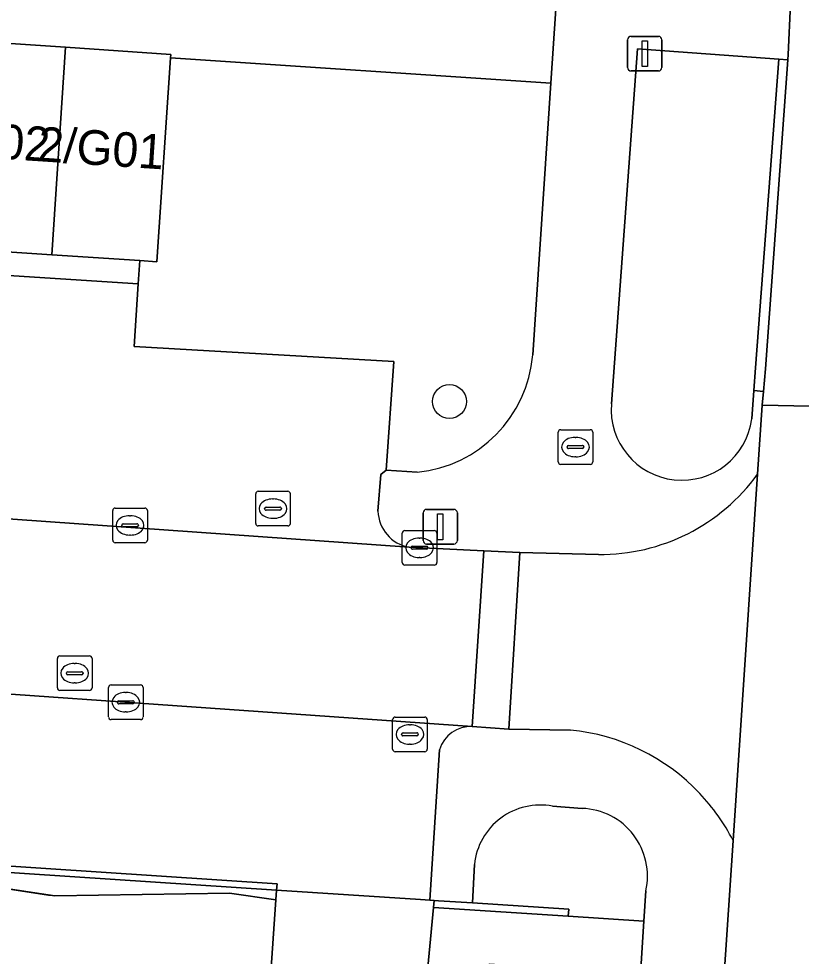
# Model space of a CAD drawing. Extents: x 161848 to 162726, y 385382 to 386521.
# Drawn here: x 162009.72 to 162032.32, y 385995.3 to 386022.36 of the extents above; entities that cross this region are included whole.
import ezdxf

# ---------------------------------------------------------------- set-up
doc = ezdxf.new("R2010")
doc.units = 0
for name, color, linetype in [('IMGEO_Boom', 7, 'Continuous'), ('IMGEO_Brandkraan', 7, 'Continuous'), ('IMGEO_Erf', 7, 'Continuous'), ('IMGEO_Fietspad_gesloten', 7, 'Continuous'), ('IMGEO_Groenvoorziening', 7, 'Continuous'), ('IMGEO_Kolk', 7, 'Continuous'), ('IMGEO_Lichtmast', 7, 'Continuous'), ('IMGEO_Muur', 7, 'Continuous'), ('IMGEO_Pand', 7, 'Continuous'), ('IMGEO_Pand_nummerreeks', 7, 'Continuous'), ('IMGEO_Pand_overbouw', 7, 'Continuous'), ('IMGEO_Parkeervlak_open', 7, 'Continuous'), ('IMGEO_Rijbaan_lokaal_open', 7, 'Continuous'), ('IMGEO_Rioolput', 7, 'Continuous'), ('IMGEO_Verkeerseiland_open', 7, 'Continuous'), ('IMGEO_Voetpad_open', 7, 'Continuous')]:
    doc.layers.add(name, color=color, linetype=linetype)

msp = doc.modelspace()

# ---------------------------------------------------------------- linework, layer by layer
at = {"layer": 'IMGEO_Boom'}
msp.add_circle((162022.162, 386011.308), 0.489, dxfattribs=at)
at = {"layer": 'IMGEO_Brandkraan'}
for p, q in [((162025.301, 386009.569), (162025.301, 386010.421)), ((162025.376, 386010.495), (162026.228, 386010.495)), ((162026.302, 386010.421), (162026.302, 386009.569)), ((162025.789, 386010.275), (162025.814, 386010.275)), ((162025.56, 386009.989), (162025.56, 386010.001)), ((162025.998, 386009.952), (162025.6, 386009.952)), ((162025.603, 386010.038), (162026.001, 386010.038)), ((162026.044, 386010.001), (162026.044, 386009.989)), ((162025.812, 386009.715), (162025.787, 386009.715)), ((162026.228, 386009.495), (162025.376, 386009.495)), ((162016.64, 386008.718), (162017.492, 386008.718)), ((162016.565, 386007.792), (162016.565, 386008.644)), ((162017.053, 386008.498), (162017.078, 386008.498)), ((162017.566, 386008.644), (162017.566, 386007.792)), ((162016.824, 386008.212), (162016.824, 386008.224)), ((162017.262, 386008.175), (162016.864, 386008.175)), ((162016.867, 386008.261), (162017.265, 386008.261)), ((162017.308, 386008.224), (162017.308, 386008.212)), ((162017.076, 386007.938), (162017.051, 386007.938)), ((162017.492, 386007.718), (162016.64, 386007.718))]:
    msp.add_line(p, q, dxfattribs=at)
for points in [[(162025.301, 386009.569), (162025.301, 386010.421)], [(162025.376, 386010.495), (162026.228, 386010.495)], [(162026.302, 386010.421), (162026.302, 386009.569)], [(162026.228, 386009.495), (162025.376, 386009.495)], [(162016.64, 386008.718), (162017.492, 386008.718)], [(162016.565, 386007.792), (162016.565, 386008.644)], [(162017.566, 386008.644), (162017.566, 386007.792)], [(162017.492, 386007.718), (162016.64, 386007.718)]]:
    msp.add_lwpolyline(points, dxfattribs=at)
for centre, radius, start, end in [((162025.378, 386010.419), 0.0765, 91.552, 178.448), ((162025.378, 386010.419), 0.0765, 91.552, 178.448), ((162026.226, 386010.419), 0.0765, 1.552, 88.448), ((162026.226, 386010.419), 0.0765, 1.552, 88.448), ((162025.6, 386009.998), 0.0403, 85.8775, 175.7526), ((162025.597, 386009.988), 0.0366, 178.938, 274.7102), ((162026.001, 386009.995), 0.043, 264.8664, 352.4533), ((162026.005, 386010), 0.0386, 1.7309, 96.639), ((162025.378, 386009.571), 0.0765, 181.552, 268.448), ((162025.378, 386009.571), 0.0765, 181.552, 268.448), ((162026.226, 386009.571), 0.0765, 271.552, 358.448), ((162026.226, 386009.571), 0.0765, 271.552, 358.448), ((162016.642, 386008.642), 0.0765, 91.552, 178.448), ((162016.642, 386008.642), 0.0765, 91.552, 178.448), ((162017.49, 386008.642), 0.0765, 1.552, 88.448), ((162017.49, 386008.642), 0.0765, 1.552, 88.448), ((162016.864, 386008.221), 0.0403, 85.8775, 175.7526), ((162016.861, 386008.211), 0.0366, 178.938, 274.7102), ((162017.265, 386008.218), 0.043, 264.8664, 352.4533), ((162017.269, 386008.223), 0.0386, 1.7309, 96.639), ((162016.642, 386007.794), 0.0765, 181.552, 268.448), ((162016.642, 386007.794), 0.0765, 181.552, 268.448), ((162017.49, 386007.794), 0.0765, 271.552, 358.448), ((162017.49, 386007.794), 0.0765, 271.552, 358.448)]:
    msp.add_arc(centre, radius, start, end, dxfattribs=at)
for centre, major_axis, ratio, start_param, end_param in [((162025.788, 386009.995), (-0.387, 0.002), 0.722429, 4.712389, 7.853982), ((162025.813, 386009.995), (-0.39, 0.002), 0.717154, 1.570796, 4.712389), ((162017.052, 386008.218), (-0.387, 0.002), 0.722429, 4.712389, 7.853982), ((162017.077, 386008.218), (-0.39, 0.002), 0.717154, 1.570796, 4.712389)]:
    msp.add_ellipse(centre, major_axis=major_axis, ratio=ratio, start_param=start_param, end_param=end_param, dxfattribs=at)
at = {"layer": 'IMGEO_Erf'}
msp.add_lwpolyline([(162008.044, 386021.736), (162011.077, 386021.533), (162014.11, 386021.33), (162014.103, 386021.229), (162025.095, 386020.494), (162030.157, 386095.724)], dxfattribs=at)
at = {"layer": 'IMGEO_Fietspad_gesloten'}
for points in [[(162039.139, 386128.803), (162036.98, 386096.379), (162036.936, 386095.719), (162035.651, 386076.246), (162035.507, 386074.767), (162034.711, 386062.651), (162034.288, 386056.532), (162034.007, 386052.459), (162033.132, 386039.976), (162033.055, 386038.516), (162032.013, 386022.792), (162031.948, 386021.324), (162031.937, 386021.171), (162031.287, 386012.253), (162031.231, 386011.601), (162031.196, 386011.202), (162034.41, 386011.138), (162040.007, 386093.754), (162040.137, 386095.676), (162041.2, 386111.341), (162042.155, 386125.42)], [(162033.303, 385994.07), (162034.41, 386011.138), (162031.196, 386011.202), (162031.063, 386009.215), (162030.355, 385998.641), (162028.943, 385977.582)]]:
    msp.add_lwpolyline(points, dxfattribs=at)
at = {"layer": 'IMGEO_Groenvoorziening'}
for points in [[(162031.673, 386021.19), (162027.596, 386021.487), (162026.839, 386011.243)], [(162024.567, 386012.654), (162025.095, 386020.494), (162014.103, 386021.229), (162013.708, 386015.343), (162013.217, 386015.376), (162013.174, 386014.703), (162013.058, 386012.9), (162020.554, 386012.466), (162020.338, 386009.331), (162021.234, 386009.269)], [(162030.896, 386010.809), (162030.957, 386011.624), (162031.006, 386012.278), (162031.673, 386021.19)], [(162025.995, 385999.567), (162025.142, 385999.63)], [(162022.881, 385997.95), (162022.829, 385996.837), (162025.606, 385996.656), (162025.594, 385996.456), (162027.776, 385996.309), (162027.833, 385997.182)]]:
    msp.add_lwpolyline(points, dxfattribs=at)
for centre, radius, start, end in [((162020.867, 386012.964), 3.713, 275.6717, 355.2152), ((162028.873, 386011.079), 2.041, 175.3959, 352.3921), ((162024.789, 385997.744), 1.919, 79.3874, 173.8398), ((162025.927, 385997.614), 1.954, 347.225, 88.0143)]:
    msp.add_arc(centre, radius, start, end, dxfattribs=at)
at = {"layer": 'IMGEO_Kolk'}
for p, q in [((162012.511, 386008.235), (162013.363, 386008.235)), ((162012.436, 386007.309), (162012.436, 386008.161)), ((162012.924, 386008.015), (162012.949, 386008.015)), ((162013.437, 386008.161), (162013.437, 386007.309)), ((162012.695, 386007.729), (162012.695, 386007.741)), ((162013.133, 386007.692), (162012.735, 386007.692)), ((162012.738, 386007.778), (162013.136, 386007.778)), ((162013.179, 386007.741), (162013.179, 386007.729)), ((162012.947, 386007.455), (162012.922, 386007.455)), ((162020.798, 386006.662), (162020.798, 386007.514)), ((162020.873, 386007.588), (162021.725, 386007.588)), ((162021.286, 386007.368), (162021.311, 386007.368)), ((162021.799, 386007.514), (162021.799, 386006.662)), ((162013.363, 386007.235), (162012.511, 386007.235)), ((162021.057, 386007.082), (162021.057, 386007.094)), ((162021.1, 386007.131), (162021.498, 386007.131)), ((162021.541, 386007.094), (162021.541, 386007.082)), ((162021.495, 386007.045), (162021.097, 386007.045)), ((162021.725, 386006.588), (162020.873, 386006.588)), ((162021.309, 386006.808), (162021.284, 386006.808)), ((162012.313, 386002.204), (162012.313, 386003.056)), ((162012.388, 386003.13), (162013.24, 386003.13)), ((162013.314, 386003.056), (162013.314, 386002.204)), ((162012.801, 386002.91), (162012.826, 386002.91)), ((162012.572, 386002.624), (162012.572, 386002.636)), ((162013.01, 386002.587), (162012.612, 386002.587)), ((162012.615, 386002.673), (162013.013, 386002.673)), ((162013.056, 386002.636), (162013.056, 386002.624)), ((162012.824, 386002.35), (162012.799, 386002.35)), ((162013.24, 386002.13), (162012.388, 386002.13)), ((162020.52, 386001.275), (162020.52, 386002.127)), ((162020.595, 386002.201), (162021.447, 386002.201)), ((162021.008, 386001.981), (162021.033, 386001.981)), ((162021.521, 386002.127), (162021.521, 386001.275)), ((162020.779, 386001.695), (162020.779, 386001.707)), ((162020.822, 386001.744), (162021.22, 386001.744)), ((162021.263, 386001.707), (162021.263, 386001.695)), ((162021.217, 386001.658), (162020.819, 386001.658)), ((162021.031, 386001.421), (162021.006, 386001.421)), ((162021.447, 386001.201), (162020.595, 386001.201))]:
    msp.add_line(p, q, dxfattribs=at)
for points in [[(162012.511, 386008.235), (162013.363, 386008.235)], [(162012.436, 386007.309), (162012.436, 386008.161)], [(162013.437, 386008.161), (162013.437, 386007.309)], [(162020.798, 386006.662), (162020.798, 386007.514)], [(162020.873, 386007.588), (162021.725, 386007.588)], [(162021.799, 386007.514), (162021.799, 386006.662)], [(162013.363, 386007.235), (162012.511, 386007.235)], [(162021.725, 386006.588), (162020.873, 386006.588)], [(162012.313, 386002.204), (162012.313, 386003.056)], [(162012.388, 386003.13), (162013.24, 386003.13)], [(162013.314, 386003.056), (162013.314, 386002.204)], [(162013.24, 386002.13), (162012.388, 386002.13)], [(162020.52, 386001.275), (162020.52, 386002.127)], [(162020.595, 386002.201), (162021.447, 386002.201)], [(162021.521, 386002.127), (162021.521, 386001.275)], [(162021.447, 386001.201), (162020.595, 386001.201)]]:
    msp.add_lwpolyline(points, dxfattribs=at)
for centre, radius, start, end in [((162012.513, 386008.159), 0.0765, 91.552, 178.448), ((162012.513, 386008.159), 0.0765, 91.552, 178.448), ((162013.361, 386008.159), 0.0765, 1.552, 88.448), ((162013.361, 386008.159), 0.0765, 1.552, 88.448), ((162012.735, 386007.738), 0.0403, 85.8775, 175.7526), ((162012.732, 386007.728), 0.0366, 178.938, 274.7102), ((162013.136, 386007.735), 0.043, 264.8664, 352.4533), ((162013.14, 386007.74), 0.0386, 1.7309, 96.639), ((162020.875, 386007.512), 0.0765, 91.552, 178.448), ((162020.875, 386007.512), 0.0765, 91.552, 178.448), ((162021.723, 386007.512), 0.0765, 1.552, 88.448), ((162021.723, 386007.512), 0.0765, 1.552, 88.448), ((162012.513, 386007.311), 0.0765, 181.552, 268.448), ((162012.513, 386007.311), 0.0765, 181.552, 268.448), ((162013.361, 386007.311), 0.0765, 271.552, 358.448), ((162013.361, 386007.311), 0.0765, 271.552, 358.448), ((162021.097, 386007.091), 0.0403, 85.8775, 175.7526), ((162021.502, 386007.093), 0.0386, 1.7309, 96.639), ((162021.094, 386007.081), 0.0366, 178.938, 274.7102), ((162021.498, 386007.088), 0.043, 264.8664, 352.4533), ((162020.875, 386006.664), 0.0765, 181.552, 268.448), ((162020.875, 386006.664), 0.0765, 181.552, 268.448), ((162021.723, 386006.664), 0.0765, 271.552, 358.448), ((162021.723, 386006.664), 0.0765, 271.552, 358.448), ((162012.39, 386003.054), 0.0765, 91.552, 178.448), ((162012.39, 386003.054), 0.0765, 91.552, 178.448), ((162013.238, 386003.054), 0.0765, 1.552, 88.448), ((162013.238, 386003.054), 0.0765, 1.552, 88.448), ((162012.612, 386002.633), 0.0403, 85.8775, 175.7526), ((162012.609, 386002.623), 0.0366, 178.938, 274.7102), ((162013.013, 386002.63), 0.043, 264.8664, 352.4533), ((162013.017, 386002.635), 0.0386, 1.7309, 96.639), ((162012.39, 386002.206), 0.0765, 181.552, 268.448), ((162012.39, 386002.206), 0.0765, 181.552, 268.448), ((162013.238, 386002.206), 0.0765, 271.552, 358.448), ((162013.238, 386002.206), 0.0765, 271.552, 358.448), ((162020.597, 386002.125), 0.0765, 91.552, 178.448), ((162020.597, 386002.125), 0.0765, 91.552, 178.448), ((162021.445, 386002.125), 0.0765, 1.552, 88.448), ((162021.445, 386002.125), 0.0765, 1.552, 88.448), ((162020.819, 386001.704), 0.0403, 85.8775, 175.7526), ((162020.816, 386001.694), 0.0366, 178.938, 274.7102), ((162021.22, 386001.701), 0.043, 264.8664, 352.4533), ((162021.224, 386001.706), 0.0386, 1.7309, 96.639), ((162020.597, 386001.277), 0.0765, 181.552, 268.448), ((162020.597, 386001.277), 0.0765, 181.552, 268.448), ((162021.445, 386001.277), 0.0765, 271.552, 358.448), ((162021.445, 386001.277), 0.0765, 271.552, 358.448)]:
    msp.add_arc(centre, radius, start, end, dxfattribs=at)
for centre, major_axis, ratio, start_param, end_param in [((162012.923, 386007.735), (-0.387, 0.002), 0.722429, 4.712389, 7.853982), ((162012.948, 386007.735), (-0.39, 0.002), 0.717154, 1.570796, 4.712389), ((162021.285, 386007.088), (-0.387, 0.002), 0.722429, 4.712389, 7.853982), ((162021.31, 386007.088), (-0.39, 0.002), 0.717154, 1.570796, 4.712389), ((162012.8, 386002.63), (-0.387, 0.002), 0.722429, 4.712389, 7.853982), ((162012.825, 386002.63), (-0.39, 0.002), 0.717154, 1.570796, 4.712389), ((162021.007, 386001.701), (-0.387, 0.002), 0.722429, 4.712389, 7.853982), ((162021.032, 386001.701), (-0.39, 0.002), 0.717154, 1.570796, 4.712389)]:
    msp.add_ellipse(centre, major_axis=major_axis, ratio=ratio, start_param=start_param, end_param=end_param, dxfattribs=at)
at = {"layer": 'IMGEO_Lichtmast'}
for p, q in [((162027.308, 386020.95), (162027.308, 386021.75)), ((162027.308, 386021.75), (162027.308, 386020.95)), ((162027.408, 386021.85), (162028.198, 386021.85)), ((162028.198, 386021.85), (162027.408, 386021.85)), ((162028.298, 386021.75), (162028.298, 386020.95)), ((162028.298, 386020.95), (162028.298, 386021.75)), ((162028.198, 386020.85), (162027.408, 386020.85)), ((162027.408, 386020.85), (162028.198, 386020.85)), ((162021.5, 386008.197), (162022.29, 386008.197)), ((162022.29, 386008.197), (162021.5, 386008.197)), ((162021.4, 386007.297), (162021.4, 386008.097)), ((162021.4, 386008.097), (162021.4, 386007.297)), ((162022.39, 386008.097), (162022.39, 386007.297)), ((162022.39, 386007.297), (162022.39, 386008.097)), ((162022.29, 386007.197), (162021.5, 386007.197)), ((162021.5, 386007.197), (162022.29, 386007.197))]:
    msp.add_line(p, q, dxfattribs=at)
for points in [[(162027.728, 386021.725), (162027.878, 386021.725), (162027.878, 386020.975), (162027.728, 386020.975), (162027.728, 386021.725)], [(162021.82, 386008.072), (162021.97, 386008.072), (162021.97, 386007.322), (162021.82, 386007.322), (162021.82, 386008.072)]]:
    msp.add_lwpolyline(points, dxfattribs=at)
for centre, start, end in [((162027.408, 386021.75), 90, 180), ((162027.408, 386021.75), 90, 180), ((162028.198, 386021.75), 0, 90), ((162028.198, 386021.75), 360, 90), ((162027.408, 386020.95), 180, 270), ((162027.408, 386020.95), 180, 270), ((162028.198, 386020.95), 270, 0), ((162028.198, 386020.95), 270, 0), ((162021.5, 386008.097), 90, 180), ((162021.5, 386008.097), 90, 180), ((162022.29, 386008.097), 0, 90), ((162022.29, 386008.097), 360, 90), ((162021.5, 386007.297), 180, 270), ((162021.5, 386007.297), 180, 270), ((162022.29, 386007.297), 270, 0), ((162022.29, 386007.297), 270, 0)]:
    msp.add_arc(centre, 0.1, start, end, dxfattribs=at)
at = {"layer": 'IMGEO_Muur'}
msp.add_lwpolyline([(162021.849, 385996.901), (162021.722, 385996.909), (162021.702, 385996.701), (162025.594, 385996.456), (162025.606, 385996.656), (162022.829, 385996.837)], close=True, dxfattribs=at)
at = {"layer": 'IMGEO_Pand'}
for points in [[(162010.676, 386015.546), (162011.077, 386021.533), (162008.044, 386021.736), (162007.643, 386015.749)], [(162013.217, 386015.376), (162013.708, 386015.343), (162014.103, 386021.229), (162014.11, 386021.33), (162011.077, 386021.533), (162010.676, 386015.546)]]:
    msp.add_lwpolyline(points, close=True, dxfattribs=at)
msp.add_lwpolyline([(162021.474, 385994.271), (162021.702, 385996.701), (162021.722, 385996.909), (162021.595, 385996.917), (162021.323, 385996.935), (162017.169, 385997.206), (162017.15, 385996.928), (162016.988, 385994.549)], dxfattribs=at)
at = {"layer": 'IMGEO_Pand_overbouw'}
msp.add_lwpolyline([(162016.988, 385994.549), (162017.15, 385996.928), (162015.805, 385997.123), (162010.761, 385997.038), (162010.583, 385997.049), (162005.757, 385997.791)], dxfattribs=at)
at = {"layer": 'IMGEO_Parkeervlak_open'}
for points in [[(162020.095, 386008.148), (162020.18, 386009.2), (162020.338, 386009.331), (162020.554, 386012.466), (162013.058, 386012.9), (162013.174, 386014.703), (162000, 386015.551), (161976.163, 386017.082), (161975.811, 386012.268)], [(161973.302, 386010.364), (162000, 386008.592), (162020.995, 386007.103)], [(162022.818, 386001.933), (162000, 386003.528), (161970.104, 386005.509)], [(162002.171, 386002.292), (162002.024, 386000), (162001.922, 385998.394), (162017.182, 385997.385), (162017.169, 385997.206), (162021.323, 385996.935), (162021.595, 385996.917), (162021.878, 386001.26)]]:
    msp.add_lwpolyline(points, dxfattribs=at)
for centre, radius, start, end in [((162021.2, 386008.189), 1.105, 182.1424, 259.3306), ((162022.785, 386000.986), 0.947, 87.9989, 163.2032)]:
    msp.add_arc(centre, radius, start, end, dxfattribs=at)
at = {"layer": 'IMGEO_Rijbaan_lokaal_open'}
for points in [[(161965.521, 386015.701), (161960.651, 386015.914), (161959.999, 386006.135), (161970.104, 386005.509), (162000, 386003.528), (162022.818, 386001.933), (162023.151, 386006.999), (162020.995, 386007.103), (162000, 386008.592)], [(162030.355, 385998.641), (162031.063, 386009.215)], [(162026.465, 386006.897), (162024.191, 386006.953), (162023.874, 386001.85), (162025.655, 386001.825)]]:
    msp.add_lwpolyline(points, dxfattribs=at)
msp.add_lwpolyline([(162023.874, 386001.85), (162024.191, 386006.953), (162023.151, 386006.999), (162022.818, 386001.933)], close=True, dxfattribs=at)
for centre, radius, start, end in [((162026.526, 386012.496), 5.6, 269.3806, 324.1277), ((162025.087, 385995.925), 5.927, 43.431, 84.4989), ((162025.061, 385995.907), 5.958, 27.3119, 43.3877)]:
    msp.add_arc(centre, radius, start, end, dxfattribs=at)
at = {"layer": 'IMGEO_Rioolput'}
for p, q in [((162010.838, 386003.042), (162010.838, 386003.894)), ((162010.913, 386003.968), (162011.765, 386003.968)), ((162011.839, 386003.894), (162011.839, 386003.042)), ((162011.326, 386003.748), (162011.351, 386003.748)), ((162011.097, 386003.462), (162011.097, 386003.474)), ((162011.535, 386003.425), (162011.137, 386003.425)), ((162011.14, 386003.511), (162011.538, 386003.511)), ((162011.581, 386003.474), (162011.581, 386003.462)), ((162011.349, 386003.188), (162011.324, 386003.188)), ((162011.765, 386002.968), (162010.913, 386002.968))]:
    msp.add_line(p, q, dxfattribs=at)
for points in [[(162010.838, 386003.042), (162010.838, 386003.894)], [(162010.913, 386003.968), (162011.765, 386003.968)], [(162011.839, 386003.894), (162011.839, 386003.042)], [(162011.765, 386002.968), (162010.913, 386002.968)]]:
    msp.add_lwpolyline(points, dxfattribs=at)
for centre, radius, start, end in [((162010.915, 386003.892), 0.0765, 91.552, 178.448), ((162010.915, 386003.892), 0.0765, 91.552, 178.448), ((162011.763, 386003.892), 0.0765, 1.552, 88.448), ((162011.763, 386003.892), 0.0765, 1.552, 88.448), ((162011.137, 386003.471), 0.0403, 85.8775, 175.7526), ((162011.134, 386003.461), 0.0366, 178.938, 274.7102), ((162011.538, 386003.468), 0.043, 264.8664, 352.4533), ((162011.542, 386003.473), 0.0386, 1.7309, 96.639), ((162010.915, 386003.044), 0.0765, 181.552, 268.448), ((162010.915, 386003.044), 0.0765, 181.552, 268.448), ((162011.763, 386003.044), 0.0765, 271.552, 358.448), ((162011.763, 386003.044), 0.0765, 271.552, 358.448)]:
    msp.add_arc(centre, radius, start, end, dxfattribs=at)
for centre, major_axis, ratio, start_param, end_param in [((162011.325, 386003.468), (-0.387, 0.002), 0.722429, 4.712389, 7.853982), ((162011.35, 386003.468), (-0.39, 0.002), 0.717154, 1.570796, 4.712389)]:
    msp.add_ellipse(centre, major_axis=major_axis, ratio=ratio, start_param=start_param, end_param=end_param, dxfattribs=at)
at = {"layer": 'IMGEO_Verkeerseiland_open'}
msp.add_lwpolyline([(162031.937, 386021.171), (162031.673, 386021.19), (162031.006, 386012.278), (162030.957, 386011.624), (162031.231, 386011.601), (162031.287, 386012.253)], close=True, dxfattribs=at)
at = {"layer": 'IMGEO_Voetpad_open'}
for points in [[(162030.157, 386095.724), (162025.095, 386020.494), (162024.567, 386012.654)], [(162026.839, 386011.243), (162027.596, 386021.487), (162031.673, 386021.19), (162031.937, 386021.171), (162031.948, 386021.324), (162032.013, 386022.792), (162031.714, 386022.812), (162027.689, 386023.077), (162028.778, 386038.763), (162032.755, 386038.533), (162033.055, 386038.516), (162033.132, 386039.976), (162032.833, 386039.997), (162028.861, 386040.269), (162029.97, 386056.852), (162033.993, 386056.554), (162034.288, 386056.532), (162034.711, 386062.651), (162034.412, 386062.671), (162030.384, 386062.943), (162031.204, 386075.033), (162035.208, 386074.786), (162035.507, 386074.767), (162035.651, 386076.246)], [(162031.063, 386009.215), (162031.196, 386011.202), (162031.231, 386011.601), (162030.957, 386011.624), (162030.896, 386010.809)], [(162021.234, 386009.269), (162020.338, 386009.331), (162020.18, 386009.2), (162020.095, 386008.148)], [(162020.995, 386007.103), (162023.151, 386006.999), (162024.191, 386006.953), (162026.465, 386006.897)], [(161970.104, 386005.509), (161959.999, 386006.135), (161954.524, 386006.517), (161954.28, 386002.809), (161962.72, 386002.241), (161970.682, 386001.705), (161970.571, 386000.289), (162017.169, 385997.206), (162017.182, 385997.385), (162001.922, 385998.394), (162002.024, 386000), (162002.171, 386002.292)], [(162025.655, 386001.825), (162023.874, 386001.85), (162022.818, 386001.933)], [(162021.878, 386001.26), (162021.595, 385996.917), (162021.722, 385996.909), (162021.849, 385996.901), (162022.829, 385996.837), (162022.881, 385997.95)], [(162005.757, 385997.791), (162010.761, 385997.038), (162015.805, 385997.123), (162017.15, 385996.928), (162017.169, 385997.206), (161970.571, 386000.289)], [(162025.142, 385999.63), (162025.995, 385999.567)], [(162028.943, 385977.582), (162030.355, 385998.641)], [(162016.988, 385994.549), (162017.15, 385996.928), (162015.805, 385997.123), (162010.761, 385997.038), (162005.757, 385997.791)], [(162027.833, 385997.182), (162027.776, 385996.309), (162027.676, 385994.782), (162026.642, 385979.005)]]:
    msp.add_lwpolyline(points, dxfattribs=at)
for points in [[(161976.163, 386017.082), (162000, 386015.551), (162013.174, 386014.703), (162013.217, 386015.376), (162010.676, 386015.546), (162007.643, 386015.749), (162004.61, 386015.952), (162001.578, 386016.155), (162000, 386016.261), (161998.545, 386016.359), (161995.511, 386016.562), (161994.009, 386016.664), (161990.973, 386016.868), (161987.936, 386017.072), (161984.9, 386017.275), (161981.864, 386017.479), (161978.827, 386017.683), (161976.22, 386017.858)], [(162027.776, 385996.309), (162025.594, 385996.456), (162021.702, 385996.701), (162021.474, 385994.271), (162023.255, 385994.15), (162023.315, 385995.076), (162027.676, 385994.782)]]:
    msp.add_lwpolyline(points, close=True, dxfattribs=at)
for centre, radius, start, end in [((162020.867, 386012.964), 3.713, 275.6717, 355.2152), ((162028.873, 386011.079), 2.041, 175.3959, 352.3921), ((162026.526, 386012.496), 5.6, 269.3806, 324.1277), ((162021.2, 386008.189), 1.105, 182.1424, 259.3306), ((162022.785, 386000.986), 0.947, 87.9989, 163.2032), ((162025.087, 385995.925), 5.927, 43.431, 84.4989), ((162025.061, 385995.907), 5.958, 27.3119, 43.3877), ((162024.789, 385997.744), 1.919, 79.3874, 173.8398), ((162025.927, 385997.614), 1.954, 347.225, 88.0143)]:
    msp.add_arc(centre, radius, start, end, dxfattribs=at)

# ---------------------------------------------------------------- texts
at = {"layer": 'IMGEO_Pand_nummerreeks'}
for s, p in [('2/G02', (162006.958, 386018.464)), ('2/G01', (162010.251, 386018.248))]:
    msp.add_text(s, height=1, rotation=356.2483, dxfattribs=at).set_placement(p)

doc.saveas('drawing.dxf')
